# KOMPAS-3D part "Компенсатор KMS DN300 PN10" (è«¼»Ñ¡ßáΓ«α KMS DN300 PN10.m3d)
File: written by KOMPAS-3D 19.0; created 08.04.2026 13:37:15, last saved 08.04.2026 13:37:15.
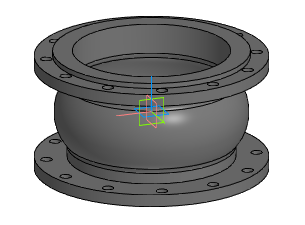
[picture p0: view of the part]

Document properties: Автор: Энергия; Полное имя файла: Z:\3.Личные\kachalov\3d для проектировщиков\7.1 Компенсатор\stp_Компенсатор KSM\Компенсатор KMS DN300 PN10.m3d

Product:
- Part/product: Компенсатор KMS DN300 PN10

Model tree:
1. Операция без истории:1  (labels: Компенсатор KMS DN300 PN10)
